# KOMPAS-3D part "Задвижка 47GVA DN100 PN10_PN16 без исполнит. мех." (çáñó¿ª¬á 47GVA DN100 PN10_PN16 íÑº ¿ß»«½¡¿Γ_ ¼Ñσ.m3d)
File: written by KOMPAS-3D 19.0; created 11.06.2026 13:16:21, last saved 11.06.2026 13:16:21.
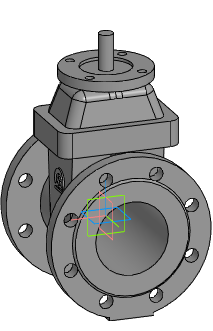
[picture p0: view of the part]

Document properties: Автор: Евгений; Полное имя файла: Z:\3.Личные\kachalov\001_3d для проектировщиков\2.2 Тип 47GVA, 47GVA.Z\_stp\_stp_Задвижка 47GVA DN40-DN1000 без исп.мех\Задвижка 47GVA DN100 PN10_PN16 без исполнит_ мех.m3d

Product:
- Part/product: Задвижка 47GVA DN100 PN10_PN16 без исполнит. мех.

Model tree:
1. Операция без истории:1  (labels: Задвижка 47GVA DN100 PN10_PN16 без исполнит. мех.)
